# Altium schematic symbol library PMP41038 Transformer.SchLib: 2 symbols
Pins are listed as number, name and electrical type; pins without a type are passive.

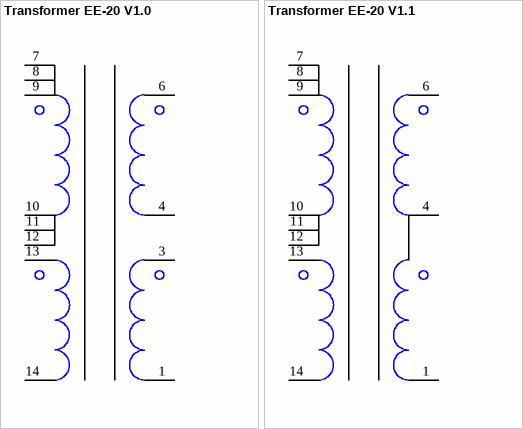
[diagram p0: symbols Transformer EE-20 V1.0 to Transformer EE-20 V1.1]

## Transformer EE-20 V1.0
designator T?, comment Used in BOM report
CompType: Used in some BOM reports.  Useful for finding later.
footprint EE20-10-6_7080 (Footprint not found)
pins: 1, 3, 4, 6, 7, 8, 9, 10, 11, 12, 13, 14

## Transformer EE-20 V1.1
designator T?, comment Used in BOM report
CompType: Used in some BOM reports.  Useful for finding later.
footprint EE20-10-6_7080 (Footprint not found)
pins: 1, 4, 6, 7, 8, 9, 10, 11, 12, 13, 14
